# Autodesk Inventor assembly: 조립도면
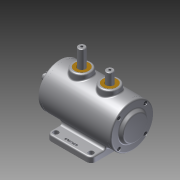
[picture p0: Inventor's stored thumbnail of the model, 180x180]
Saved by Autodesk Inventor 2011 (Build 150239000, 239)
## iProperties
Created: 2014-12
Part Number: 조립도면
Document SubType Name: Assembly
Designer: user
Author: user
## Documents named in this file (10)
- D:\441225V1003\조립도면.iam
- D:\441225V1003\1.본체.ipt
- D:\441225V1003\2.축.ipt
- D:\441225V1003\뒷커버.ipt
- D:\441225V1003\베어링 6203.ipt
- D:\441225V1003\부시.ipt
- D:\441225V1003\슬라이더.ipt
- D:\441225V1003\앞커버.ipt
- D:\441225V1003\오일실.ipt
- D:\441225V1003\M4-소켓머리.ipt
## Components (13 placed, 5 different names)
1. 1.본체:1
2. 2.축:1
3. 7-베어링 6203:1
4. 8-오일실:1
5. 7-베어링 6203:2
6. 9-M4-소켓머리:2
7. 9-M4-소켓머리:4
8. 9-M4-소켓머리:5
9. 9-M4-소켓머리:6
10. 9-M4-소켓머리:3
11. 9-M4-소켓머리:7
12. 9-M4-소켓머리:8
13. 9-M4-소켓머리:9
